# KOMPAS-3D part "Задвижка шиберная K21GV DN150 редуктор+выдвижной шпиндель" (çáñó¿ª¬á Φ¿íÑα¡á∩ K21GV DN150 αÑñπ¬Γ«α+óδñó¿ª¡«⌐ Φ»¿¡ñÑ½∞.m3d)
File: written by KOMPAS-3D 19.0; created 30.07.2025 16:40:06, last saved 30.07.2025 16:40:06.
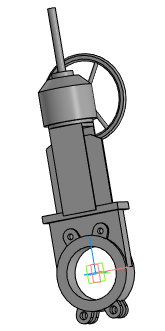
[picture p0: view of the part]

Document properties: Полное имя файла: Задвижка шиберная K21GV DN150 редуктор+выдвижной шпиндель.a3d

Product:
- Part/product: Задвижка шиберная K21GV DN150 редуктор+выдвижной шпиндель
    Масса: 39.4157

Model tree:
1. Операция без истории:1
